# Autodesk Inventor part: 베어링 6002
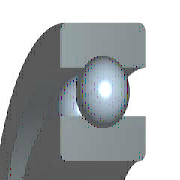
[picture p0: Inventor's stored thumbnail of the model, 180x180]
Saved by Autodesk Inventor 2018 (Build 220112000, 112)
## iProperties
Created: 2012-02
Part Number: 베어링 6002
Material: 강철, 연강
Description: 깊은 그루브 볼 베어링
Document SubType Name: Modeling
Standard: KS B 2023
Designer: mduedu
Standards Organization: KS
Language: ko-KR
Size Designation: 6002 - 15 x 32 x 9
Categories: <MemberInstance><Categories><Category DisplayName="샤프트 부품" InternalName="7f7aeb1f-a693-4053-b835-cee3144e0d98" Mnemonic="SHFT"><Category DisplayName="베어링" Inter
Density: 7.86 g/cm^3
Mass: 29.8124 g
Surface Area: 39.9079 cm^2
Volume: 3.79293 cm^3
Appearance: 분홍색
IsCustomPart: 1
Author: mduedu
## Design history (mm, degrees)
sketch "스케치" dims "d0" = 4.42 (= -0.26 x WD + 0.26 x BD)
  geometry: L1 (2.29, 11.75)-(6.71, 11.75); L2 (4.5, 11.75)-(4.5, 9.54); L3 (4.5, 11.75)-(4.5, 13.96); L4 (2.858, 10.271)-(0, 10.271); L5 (0, 7.5)-(9, 7.5); L6 (2.858, 13.229)-(0, 13.229); L7 (0, 16)-(9, 16); L8 (9, 7.5)-(9, 10.271); L9 (6.142, 10.271)-(9, 10.271); L10 (6.142, 13.229)-(9, 13.229); L11 (9, 16)-(9, 13.229); L12 (-1.4, 0)-(8.4, 0) reference; L13 (0, -0.3)-(0, 5.3) reference
  constraints: 22 end point, 4 point on line, 2 collinear, 2 perpendicular, 2 symmetric about line, 1 midpoint, 1 parallel, 14 other
  dimensions: "d9" = 15 diameter of L5 L12 (= WD); "d11" = 32 diameter of L7 L12 (= BD); "d12" = 9 distance between parallel lines of L8 L13 (= KB); "d13" = 20.542 diameter of L9 L12 (= 0.326 x BD + 0.674 x WD)
revolve "본체" stored, may be unused: angle "d6" = 90 deg
revolve "볼" stored, may be unused: angle "d7" = 90 deg
pattern_circular "IDS_ARRAYBALL[SIMPL:T]" dims angle "d3" = 360 deg
body "Solid1"
fillet "모깎기1" dims "d1" = 0.3 (= KRS)
other parameters: "WD" = 15 [user parameter; used in 5 equation terms], "BD" = 32 [user parameter; used in 5 equation terms], "KB" = 9 [user parameter; used in 1 equation term], "KRS" = 0.3 [user parameter; used in 1 equation term], "d4" = 0, "d5" = 0, "d8" = 0, "d14" = 0, "d15" = 0, "BBA" = 0 [user parameter], "BC0" = 2850000 [user parameter], "BC" = 5590000 [user parameter], "BR" = 16 (= 0.5 x BD) [user parameter], "WR" = 7.5 (= 0.5 x WD) [user parameter]
